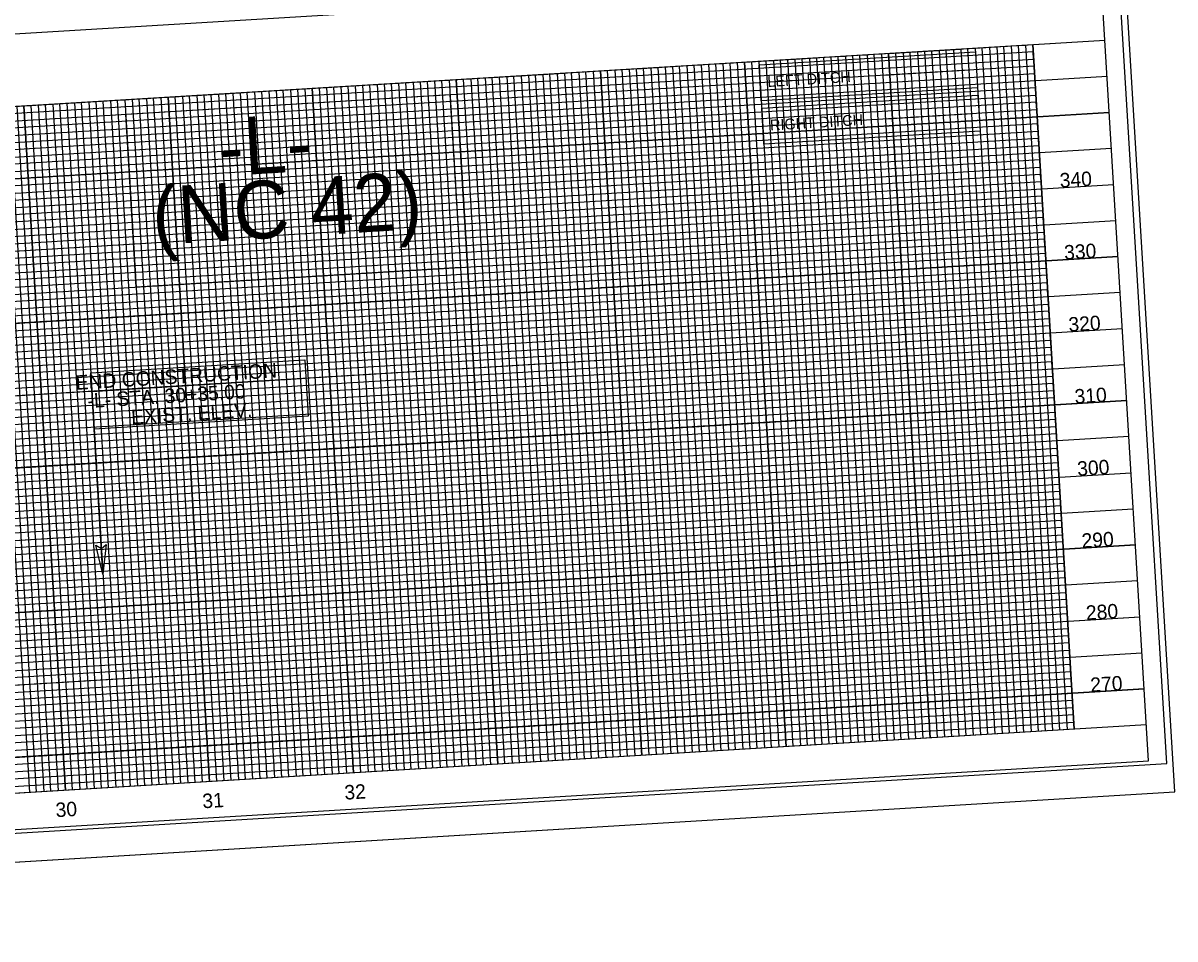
# Model space of a CAD drawing. Extents: x 2111349 to 2114115, y 669753 to 671326.
# Drawn here: x 2113118 to 2113916, y 669753 to 670387 of the extents above; entities that cross this region are included whole.
import ezdxf

# ---------------------------------------------------------------- set-up
doc = ezdxf.new("R2010")
doc.units = 0
for name, color, linetype in [('Exist Building', 7, 'Continuous'), ('Exist Building Leader', 7, 'Continuous'), ('Exist Guardrail', 7, 'Continuous'), ('Exist Other Culture Area Outline', 7, 'Continuous'), ('Exist Other Culture Area Outline Leader', 7, 'Continuous'), ('Exist Other Culture Area Outline Text', 7, 'Continuous'), ('Exist Other Culture Sign Leader', 7, 'Continuous'), ('Exist Roads Curbs', 7, 'Continuous'), ('Exist Roads Curbs Text', 7, 'Continuous'), ('Exist Roads EOP Other Text', 7, 'Continuous'), ('Exist Structure Minor Footbridge', 7, 'Continuous'), ('Exist Structure Minor Pipes CMP 60 Inch', 7, 'Continuous'), ('Exist Utilities TV Hand Hole CELL', 7, 'Continuous'), ('Exist Utilities TV Test Hole SUE LOS A Text', 7, 'Continuous'), ('Exist Utilities Water Fire Hydrant Cogo Number', 7, 'Continuous'), ('Exist Utilities Water Test Hole SUE LOS A Text', 7, 'Continuous'), ('Exist Vegetation Woods Line', 7, 'Continuous')]:
    doc.layers.add(name, color=color, linetype=linetype)

msp = doc.modelspace()

# ---------------------------------------------------------------- linework, layer by layer
at = {"layer": 'Exist Building'}
for points in [[(2112369.73, 670284.33), (2113866.98, 670375.07)], [(2113745.99, 669891.86), (2113717.25, 670365.99), (2113767.16, 670369.02), (2113795.9, 669894.89)], [(2113845.81, 669897.91), (2113817.07, 670372.04)], [(2113646.17, 669885.81), (2113617.44, 670359.94), (2113667.35, 670362.97), (2113696.08, 669888.84)], [(2113546.36, 669879.76), (2113517.62, 670353.89), (2113567.53, 670356.92), (2113596.26, 669882.79)], [(2113346.72, 669867.67), (2113317.99, 670341.8), (2113367.9, 670344.82), (2113396.63, 669870.69)], [(2113446.54, 669873.72), (2113417.8, 670347.85), (2113467.71, 670350.87), (2113496.45, 669876.74)], [(2113246.91, 669861.62), (2113218.17, 670335.75), (2113268.08, 670338.77), (2113296.81, 669864.64)], [(2113147.09, 669855.57), (2113118.35, 670329.7), (2113168.26, 670332.72), (2113197, 669858.59)], [(2113870, 670325.16), (2112372.75, 670234.42), (2112375.78, 670184.51), (2113873.03, 670275.25)], [(2113876.05, 670225.34), (2112378.8, 670134.6), (2112381.83, 670084.69), (2113879.08, 670175.43)], [(2113882.1, 670125.53), (2112384.85, 670034.78), (2112387.88, 669984.87), (2113885.13, 670075.62)], [(2113888.15, 670025.71), (2112390.9, 669934.97), (2112393.93, 669885.06), (2113891.18, 669975.8)], [(2113894.2, 669925.89), (2112396.95, 669835.15)]]:
    msp.add_lwpolyline(points, dxfattribs=at)
at = {"layer": 'Exist Building Leader'}
for points in [[(2112420.24, 670277.37), (2113817.68, 670362.06), (2113817.37, 670367.05), (2112419.94, 670282.36)], [(2113760.96, 669892.77), (2113732.23, 670366.9), (2113737.22, 670367.2), (2113765.95, 669893.07)], [(2113775.93, 669893.68), (2113747.2, 670367.81), (2113752.19, 670368.11), (2113780.93, 669893.98)], [(2113785.92, 669894.28), (2113757.18, 670368.41), (2113762.17, 670368.72), (2113790.91, 669894.59)], [(2113800.89, 669895.19), (2113772.15, 670369.32), (2113777.14, 670369.62), (2113805.88, 669895.49)], [(2113810.87, 669895.8), (2113782.14, 670369.93), (2113787.13, 670370.23), (2113815.86, 669896.1)], [(2113825.84, 669896.7), (2113797.11, 670370.83), (2113802.1, 670371.14), (2113830.83, 669897.01)], [(2113835.82, 669897.31), (2113807.09, 670371.44), (2113812.08, 670371.74), (2113840.82, 669897.61)], [(2113626.21, 669884.6), (2113597.47, 670358.73), (2113602.47, 670359.04), (2113631.2, 669884.91)], [(2113636.19, 669885.21), (2113607.46, 670359.34), (2113612.45, 670359.64), (2113641.18, 669885.51)], [(2113651.16, 669886.12), (2113622.43, 670360.25), (2113627.42, 670360.55), (2113656.15, 669886.42)], [(2113661.15, 669886.72), (2113632.41, 670360.85), (2113637.4, 670361.15), (2113666.14, 669887.02)], [(2113676.12, 669887.63), (2113647.38, 670361.76), (2113652.37, 670362.06), (2113681.11, 669887.93)], [(2113686.1, 669888.23), (2113657.36, 670362.36), (2113662.36, 670362.67), (2113691.09, 669888.54)], [(2113701.07, 669889.14), (2113672.34, 670363.27), (2113677.33, 670363.57), (2113706.06, 669889.44)], [(2113711.05, 669889.75), (2113682.32, 670363.88), (2113687.31, 670364.18), (2113716.04, 669890.05)], [(2113726.03, 669890.65), (2113697.29, 670364.78), (2113702.28, 670365.09), (2113731.02, 669890.96)], [(2113736.01, 669891.26), (2113707.27, 670365.39), (2113712.26, 670365.69), (2113741, 669891.56)], [(2113750.98, 669892.17), (2113722.25, 670366.3), (2113727.24, 670366.6), (2113755.97, 669892.47)], [(2112420.85, 670267.39), (2113818.28, 670352.08), (2113817.98, 670357.07), (2112420.54, 670272.38)], [(2113501.44, 669877.04), (2113472.7, 670351.17), (2113477.69, 670351.48), (2113506.43, 669877.35)], [(2113511.42, 669877.65), (2113482.68, 670351.78), (2113487.68, 670352.08), (2113516.41, 669877.95)], [(2113526.39, 669878.56), (2113497.66, 670352.69), (2113502.65, 670352.99), (2113531.38, 669878.86)], [(2113536.37, 669879.16), (2113507.64, 670353.29), (2113512.63, 670353.59), (2113541.37, 669879.46)], [(2113551.35, 669880.07), (2113522.61, 670354.2), (2113527.6, 670354.5), (2113556.34, 669880.37)], [(2113561.33, 669880.67), (2113532.59, 670354.8), (2113537.58, 670355.1), (2113566.32, 669880.97)], [(2113576.3, 669881.58), (2113547.57, 670355.71), (2113552.56, 670356.01), (2113581.29, 669881.88)], [(2113586.28, 669882.18), (2113557.55, 670356.31), (2113562.54, 670356.62), (2113591.27, 669882.49)], [(2113601.26, 669883.09), (2113572.52, 670357.22), (2113577.51, 670357.52), (2113606.25, 669883.39)], [(2113611.24, 669883.7), (2113582.5, 670357.83), (2113587.49, 670358.13), (2113616.23, 669884)], [(2113361.69, 669868.57), (2113332.96, 670342.7), (2113337.95, 670343.01), (2113366.69, 669868.88)], [(2113376.67, 669869.48), (2113347.93, 670343.61), (2113352.92, 670343.91), (2113381.66, 669869.78)], [(2113386.65, 669870.09), (2113357.91, 670344.22), (2113362.9, 670344.52), (2113391.64, 669870.39)], [(2113401.62, 669870.99), (2113372.89, 670345.12), (2113377.88, 670345.43), (2113406.61, 669871.3)], [(2113411.6, 669871.6), (2113382.87, 670345.73), (2113387.86, 670346.03), (2113416.59, 669871.9)], [(2113426.58, 669872.51), (2113397.84, 670346.64), (2113402.83, 670346.94), (2113431.57, 669872.81)], [(2113436.56, 669873.11), (2113407.82, 670347.24), (2113412.81, 670347.54), (2113441.55, 669873.41)], [(2113451.53, 669874.02), (2113422.79, 670348.15), (2113427.79, 670348.45), (2113456.52, 669874.32)], [(2113461.51, 669874.62), (2113432.78, 670348.75), (2113437.77, 670349.06), (2113466.5, 669874.93)], [(2113476.48, 669875.53), (2113447.75, 670349.66), (2113452.74, 670349.96), (2113481.48, 669875.83)], [(2113486.47, 669876.14), (2113457.73, 670350.27), (2113462.72, 670350.57), (2113491.46, 669876.44)], [(2112421.75, 670252.41), (2113819.19, 670337.11), (2113818.89, 670342.1), (2112421.45, 670257.41)], [(2113236.92, 669861.01), (2113208.19, 670335.14), (2113213.18, 670335.44), (2113241.91, 669861.31)], [(2113251.9, 669861.92), (2113223.16, 670336.05), (2113228.15, 670336.35), (2113256.89, 669862.22)], [(2113261.88, 669862.52), (2113233.14, 670336.65), (2113238.13, 670336.96), (2113266.87, 669862.83)], [(2113276.85, 669863.43), (2113248.12, 670337.56), (2113253.11, 670337.86), (2113281.84, 669863.73)], [(2113286.83, 669864.04), (2113258.1, 670338.17), (2113263.09, 670338.47), (2113291.82, 669864.34)], [(2113301.8, 669864.94), (2113273.07, 670339.07), (2113278.06, 670339.38), (2113306.8, 669865.25)], [(2113311.79, 669865.55), (2113283.05, 670339.68), (2113288.04, 670339.98), (2113316.78, 669865.85)], [(2113326.76, 669866.46), (2113298.02, 670340.59), (2113303.01, 670340.89), (2113331.75, 669866.76)], [(2113336.74, 669867.06), (2113308.01, 670341.19), (2113313, 670341.49), (2113341.73, 669867.36)], [(2113351.71, 669867.97), (2113322.98, 670342.1), (2113327.97, 670342.4), (2113356.7, 669868.27)], [(2112422.36, 670242.43), (2113819.79, 670327.13), (2113819.49, 670332.12), (2112422.06, 670247.42)], [(2113127.13, 669854.36), (2113098.39, 670328.49), (2113103.38, 670328.79), (2113132.12, 669854.66)], [(2113137.11, 669854.96), (2113108.37, 670329.09), (2113113.36, 670329.39), (2113142.1, 669855.26)], [(2113152.08, 669855.87), (2113123.34, 670330), (2113128.34, 670330.3), (2113157.07, 669856.17)], [(2113162.06, 669856.47), (2113133.33, 670330.6), (2113138.32, 670330.91), (2113167.05, 669856.78)], [(2113177.03, 669857.38), (2113148.3, 670331.51), (2113153.29, 670331.81), (2113182.02, 669857.68)], [(2113187.02, 669857.99), (2113158.28, 670332.12), (2113163.27, 670332.42), (2113192.01, 669858.29)], [(2113201.99, 669858.89), (2113173.25, 670333.02), (2113178.24, 670333.33), (2113206.98, 669859.2)], [(2113211.97, 669859.5), (2113183.23, 670333.63), (2113188.23, 670333.93), (2113216.96, 669859.8)], [(2113226.94, 669860.41), (2113198.21, 670334.54), (2113203.2, 670334.84), (2113231.93, 669860.71)], [(2112423.27, 670227.46), (2113820.7, 670312.15), (2113820.4, 670317.14), (2112422.96, 670232.45)], [(2112423.87, 670217.48), (2113821.31, 670302.17), (2113821, 670307.16), (2112423.57, 670222.47)], [(2112424.78, 670202.51), (2113822.21, 670287.2), (2113821.91, 670292.19), (2112424.48, 670207.5)], [(2112425.38, 670192.52), (2113822.82, 670277.22), (2113822.52, 670282.21), (2112425.08, 670197.52)], [(2112425.99, 670182.54), (2113823.42, 670267.24)], [(2112426.59, 670172.56), (2113824.03, 670257.25), (2113823.73, 670262.25), (2112426.29, 670177.55)], [(2112427.5, 670157.59), (2113824.94, 670242.28), (2113824.33, 670252.26), (2112426.89, 670167.57)], [(2112428.1, 670147.61), (2113825.54, 670232.3), (2113825.24, 670237.29), (2112427.8, 670152.6)], [(2112429.01, 670132.63), (2113826.45, 670217.33), (2113825.84, 670227.31), (2112428.41, 670142.62)], [(2112429.62, 670122.65), (2113827.05, 670207.35), (2113826.75, 670212.34), (2112429.31, 670127.64)], [(2112430.52, 670107.68), (2113827.96, 670192.37), (2113827.36, 670202.35), (2112429.92, 670117.66)], [(2112431.13, 670097.7), (2113828.57, 670182.39), (2113828.26, 670187.38), (2112430.83, 670102.69)], [(2112432.04, 670082.73), (2113829.47, 670167.42), (2113828.87, 670177.4), (2112431.43, 670092.71)], [(2112432.64, 670072.74), (2113830.08, 670157.44), (2113829.78, 670162.43), (2112432.34, 670077.73)], [(2112433.55, 670057.77), (2113830.99, 670142.46), (2113830.38, 670152.45), (2112432.94, 670067.75)], [(2112434.15, 670047.79), (2113831.59, 670132.48), (2113831.29, 670137.47), (2112433.85, 670052.78)], [(2112435.06, 670032.82), (2113832.5, 670117.51), (2113831.89, 670127.49), (2112434.46, 670042.8)], [(2112435.67, 670022.84), (2113833.1, 670107.53), (2113832.8, 670112.52), (2112435.36, 670027.83)], [(2112436.57, 670007.86), (2113834.01, 670092.56), (2113833.41, 670102.54), (2112435.97, 670017.84)], [(2112437.18, 669997.88), (2113834.61, 670082.57), (2113834.31, 670087.57), (2112436.88, 670002.87)], [(2112438.09, 669982.91), (2113835.52, 670067.6), (2113834.92, 670077.58), (2112437.48, 669992.89)], [(2112438.69, 669972.93), (2113836.13, 670057.62), (2113835.82, 670062.61), (2112438.39, 669977.92)], [(2112439.6, 669957.95), (2113837.03, 670042.65), (2113836.43, 670052.63), (2112438.99, 669967.94)], [(2112440.2, 669947.97), (2113837.64, 670032.67), (2113837.34, 670037.66), (2112439.9, 669952.96)], [(2112441.11, 669933), (2113838.55, 670017.69), (2113837.94, 670027.68), (2112440.51, 669942.98)], [(2112441.72, 669923.02), (2113839.15, 670007.71), (2113838.85, 670012.7), (2112441.41, 669928.01)], [(2112442.62, 669908.05), (2113840.06, 669992.74), (2113839.45, 670002.72), (2112442.02, 669918.03)], [(2112443.23, 669898.06), (2113840.66, 669982.76), (2113840.36, 669987.75), (2112442.93, 669903.06)], [(2112444.14, 669883.09), (2113841.57, 669967.79), (2113840.97, 669977.77), (2112443.53, 669893.07)], [(2112448.07, 669818.21), (2113845.5, 669902.9), (2113845.2, 669907.9), (2112447.77, 669823.2), (2112447.46, 669828.19), (2113844.9, 669912.89), (2113844.6, 669917.88), (2112447.16, 669833.18), (2112446.86, 669838.17), (2112446.56, 669843.17), (2113843.99, 669927.86), (2113843.69, 669932.85), (2112446.25, 669848.16), (2112445.95, 669853.15), (2113843.39, 669937.84), (2113843.08, 669942.83), (2112445.65, 669858.14), (2112445.35, 669863.13), (2112445.04, 669868.12), (2113842.48, 669952.81), (2113842.18, 669957.8), (2112444.74, 669873.11), (2112444.44, 669878.1), (2113841.87, 669962.79)]]:
    msp.add_lwpolyline(points, dxfattribs=at)
at = {"layer": 'Exist Other Culture Area Outline'}
for p, q in [((2112371.24, 670259.37), (2113868.49, 670350.11)), ((2113871.52, 670300.21), (2112374.26, 670209.46)), ((2112377.29, 670159.55), (2113874.54, 670250.3)), ((2113877.57, 670200.39), (2112380.31, 670109.65)), ((2112383.34, 670059.74), (2113880.59, 670150.48)), ((2113883.62, 670100.57), (2112386.36, 670009.83)), ((2112389.39, 669959.92), (2113886.64, 670050.66)), ((2113889.67, 670000.76), (2112392.41, 669910.01)), ((2112395.44, 669860.1), (2113892.69, 669950.85))]:
    msp.add_line(p, q, dxfattribs=at)
for points in [[(2113770.94, 669893.38), (2113742.21, 670367.51), (2113792.12, 670370.53), (2113820.85, 669896.4)], [(2113671.13, 669887.33), (2113642.39, 670361.46), (2113692.3, 670364.48), (2113721.04, 669890.35)], [(2113471.49, 669875.23), (2113442.76, 670349.36), (2113492.67, 670352.38), (2113521.4, 669878.25)], [(2113571.31, 669881.28), (2113542.57, 670355.41), (2113592.48, 670358.43), (2113621.22, 669884.3)], [(2113371.68, 669869.18), (2113342.94, 670343.31), (2113392.85, 670346.33), (2113421.58, 669872.2)], [(2113271.86, 669863.13), (2113243.12, 670337.26), (2113293.03, 670340.28), (2113321.77, 669866.15)], [(2113072.23, 669851.03), (2113043.49, 670325.16), (2113093.4, 670328.18), (2113122.13, 669854.05)], [(2113172.04, 669857.08), (2113143.31, 670331.21), (2113193.22, 670334.23), (2113221.95, 669860.1)]]:
    msp.add_lwpolyline(points, dxfattribs=at)
at = {"layer": 'Exist Other Culture Area Outline Leader'}
msp.add_line((2113165.42, 670131.73), (2113310.69, 670140.75), dxfattribs=at)
at = {"layer": 'Exist Other Culture Area Outline Text'}
msp.add_line((2113173.07, 670005.41), (2113166.99, 670105.71), dxfattribs=at)
at = {"layer": 'Exist Other Culture Sign Leader'}
msp.add_lwpolyline([(2112419.64, 670287.35), (2113817.07, 670372.04), (2113845.81, 669897.91), (2112448.37, 669813.22)], close=True, dxfattribs=at)
at = {"layer": 'Exist Roads Curbs'}
msp.add_line((2112235.14, 669752.71), (2113915.56, 669854.55), dxfattribs=at)
at = {"layer": 'Exist Roads Curbs Text'}
msp.add_line((2113895.71, 669900.94), (2112398.46, 669810.2), dxfattribs=at)
msp.add_lwpolyline([(2113833.71, 670924.06), (2112336.45, 670833.32), (2112399.97, 669785.24), (2113897.23, 669875.98)], close=True, dxfattribs=at)
at = {"layer": 'Exist Roads EOP Other Text'}
msp.add_lwpolyline([(2112246.91, 669773.46), (2113909.86, 669874.24), (2113846.03, 670927.31), (2112183.08, 670826.53)], close=True, dxfattribs=at)
at = {"layer": 'Exist Structure Minor Pipes CMP 60 Inch'}
for points in [[(2113627.57, 670358.05), (2113777.3, 670367.13), (2113778.81, 670342.17), (2113629.08, 670333.1)], [(2113188.83, 670323.95), (2113413.42, 670337.56), (2113420.68, 670217.78), (2113196.09, 670204.17)], [(2113629.39, 670328.11), (2113779.11, 670337.18), (2113780.62, 670312.23), (2113630.9, 670303.15)], [(2113164.62, 670144.83), (2113312.96, 670153.82), (2113315.33, 670114.7), (2113166.99, 670105.71)]]:
    msp.add_lwpolyline(points, close=True, dxfattribs=at)
at = {"layer": 'Exist Utilities TV Hand Hole CELL'}
for p, q in [((2112369.73, 670284.33), (2113866.98, 670375.07)), ((2113767.16, 670369.02), (2113795.9, 669894.89)), ((2113817.07, 670372.04), (2113845.81, 669897.91)), ((2113617.44, 670359.94), (2113646.17, 669885.81)), ((2113667.35, 670362.97), (2113696.08, 669888.84)), ((2113717.25, 670365.99), (2113745.99, 669891.86)), ((2113517.62, 670353.89), (2113546.36, 669879.76)), ((2113567.53, 670356.92), (2113596.26, 669882.79)), ((2113367.9, 670344.82), (2113396.63, 669870.69)), ((2113417.8, 670347.85), (2113446.54, 669873.72)), ((2113467.71, 670350.87), (2113496.45, 669876.74)), ((2113218.17, 670335.75), (2113246.91, 669861.62)), ((2113268.08, 670338.77), (2113296.81, 669864.64)), ((2113317.99, 670341.8), (2113346.72, 669867.67)), ((2113118.35, 670329.7), (2113147.09, 669855.57)), ((2113168.26, 670332.72), (2113197, 669858.59)), ((2112372.75, 670234.42), (2113870, 670325.16)), ((2112375.78, 670184.51), (2113873.03, 670275.25)), ((2112378.8, 670134.6), (2113876.05, 670225.34)), ((2112381.83, 670084.69), (2113879.08, 670175.43)), ((2112384.85, 670034.78), (2113882.1, 670125.53)), ((2112387.88, 669984.87), (2113885.13, 670075.62)), ((2112390.9, 669934.97), (2113888.15, 670025.71)), ((2112393.93, 669885.06), (2113891.18, 669975.8)), ((2112396.95, 669835.15), (2113894.2, 669925.89))]:
    msp.add_line(p, q, dxfattribs=at)
at = {"layer": 'Exist Utilities TV Test Hole SUE LOS A Text'}
msp.add_lwpolyline([(2112416.61, 670337.26), (2112389.39, 670786.43), (2113587.14, 670859.03), (2113596.22, 670709.25), (2113795.9, 670721.35), (2113814.05, 670421.95)], close=True, dxfattribs=at)
at = {"layer": 'Exist Utilities Water Fire Hydrant Cogo Number'}
msp.add_lwpolyline([(2113175.32, 670025.84), (2113173.07, 670005.41), (2113168.24, 670025.52), (2113171.99, 670023.16)], close=True, dxfattribs=at)
at = {"layer": 'Exist Utilities Water Test Hole SUE LOS A Text'}
msp.add_lwpolyline([(2112235.14, 669752.71), (2113915.56, 669854.55), (2113849.32, 670947.55), (2112168.9, 670845.7)], close=True, dxfattribs=at)
at = {"layer": 'Exist Vegetation Woods Line'}
for p, q in [((2113713.71, 670350.95), (2113773.6, 670354.58)), ((2113715.54, 670320.66), (2113775.43, 670324.29)), ((2113630.29, 670313.14), (2113630.29, 670313.14))]:
    msp.add_line(p, q, dxfattribs=at)

# ---------------------------------------------------------------- texts
at = {"layer": 'Exist Guardrail'}
for s, p in [('340', (2113836.04, 670273.01)), ('330', (2113839.07, 670223.1)), ('320', (2113842.09, 670173.19)), ('310', (2113846.31, 670123.36)), ('300', (2113848.14, 670073.38)), ('290', (2113851.17, 670023.47)), ('280', (2113854.19, 669973.56)), ('270', (2113857.22, 669923.65))]:
    msp.add_text(s, height=10, rotation=3.46824, dxfattribs=at).set_placement(p)
at = {"layer": 'Exist Other Culture Area Outline Text'}
for s, height, rotation, p in [('-L-', 40, 3.46824, (2113253.73, 670280.81)), ('(NC 42)', 40, 3.46824, (2113208.26, 670233.23)), ('  END CONSTRUCTION', 10, 3.55203, (2113147.1, 670132.52)), ('    -L- STA. 30+35.00', 10, 3.55203, (2113147.88, 670119.44)), ('EXIST. ELEV.', 10, 3.55203, (2113192.93, 670109.1))]:
    msp.add_text(s, height=height, rotation=rotation, dxfattribs=at).set_placement(p)
at = {"layer": 'Exist Structure Minor Footbridge'}
for s, p in [('32', (2113340.61, 669849.14)), ('31', (2113242.24, 669843.18)), ('30', (2113140.59, 669837.02))]:
    msp.add_text(s, height=10, rotation=3.46824, dxfattribs=at).set_placement(p)
at = {"layer": 'Exist Vegetation Woods Line'}
for s, p in [('LEFT DITCH', (2113633.51, 670342.69)), ('RIGHT DITCH', (2113635.34, 670312.54))]:
    msp.add_text(s, height=7.485, rotation=3.46824, dxfattribs=at).set_placement(p)

doc.saveas('drawing.dxf')
